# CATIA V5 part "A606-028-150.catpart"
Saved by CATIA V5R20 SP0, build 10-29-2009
Part number: A606-028-150
Source: Unknown
Property "ARTICLENO": "A606-028-150"
Property "BOMINFO": "A606-028-150"
Property "CODE": "A606-028-150"
Property "HOLES": "2"
Property "L": "150.000"
Property "L1": "25.000"
Property "L2": "100.000"
Property "LINA": "A606-028-150"
Property "NB": "A606-028-150"
Property "NBSYN": "$CODE."
Property "NN": "A606"
Property "NT": "Wear Plates, self-lubricating"
Property "SCREW": "2xM6"
Property "SUPPLIER": "CF"
Property "W": "28.000"
Bounding box of the stored display mesh (mm): x -14 to 14, y -5 to 5, z -75 to 75
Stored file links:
  C:\Users\Utente\Desktop\3D files A606\A606-028-150.catpart
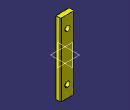
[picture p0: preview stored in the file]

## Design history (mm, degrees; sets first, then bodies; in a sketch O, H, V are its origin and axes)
Body1 "Geometry.1" (main body)
  Solid1 "A606-028-150.catpart": solid without history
